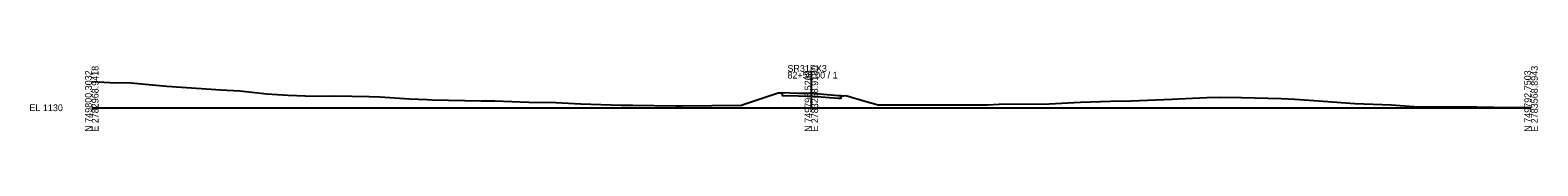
# Model space of a CAD drawing. Extents: x 1199974 to 1204603, y 1199988 to 1202535.
# Drawn here: x 1203974 to 1204603, y 1201490 to 1201518 of the extents above; entities that cross this region are included whole.
import ezdxf

# ---------------------------------------------------------------- set-up
doc = ezdxf.new("R2010")
doc.units = 0
for name, color, linetype in [('Section', 7, 'Continuous'), ('SURVEY - DTM GRAPHICS - Triangles', 7, 'Continuous'), ('SURVEY - TRANSPORTATION - Features', 7, 'Continuous'), ('XSCell', 7, 'Continuous')]:
    doc.layers.add(name, color=color, linetype=linetype)

msp = doc.modelspace()

# ---------------------------------------------------------------- linework, layer by layer
at = {"layer": 'SURVEY - DTM GRAPHICS - Triangles'}
for points in [[(1204000, 1201510.95), (1204007.52, 1201510.54), (1204016.42, 1201510.36), (1204017.78, 1201510.23), (1204031.32, 1201508.94), (1204053.76, 1201507.5), (1204059.13, 1201507.19), (1204061.69, 1201507.01), (1204072.99, 1201505.86), (1204081.91, 1201505.29), (1204092.53, 1201504.81), (1204101.17, 1201505), (1204115.62, 1201504.76), (1204120.15, 1201504.54), (1204132.44, 1201503.79), (1204139.75, 1201503.45), (1204141.88, 1201503.35), (1204162.35, 1201502.94), (1204168.08, 1201502.85), (1204182.13, 1201502.29), (1204193.45, 1201502.14), (1204203.82, 1201501.7), (1204220.71, 1201501.14), (1204225.49, 1201501.02), (1204243.49, 1201500.83), (1204245.31, 1201500.82), (1204246.19, 1201500.81), (1204270.79, 1201501.1), (1204272.33, 1201501.69), (1204286.11, 1201506.18), (1204287.09, 1201506.17), (1204287.85, 1201506.17)], [(1204312.36, 1201504.96), (1204312.72, 1201504.97), (1204312.99, 1201504.99), (1204313.56, 1201505.01), (1204314.3, 1201505.06), (1204322.89, 1201502.65), (1204327.87, 1201501.25), (1204337.19, 1201501.27), (1204347.94, 1201501.29), (1204356.83, 1201501.28), (1204373.46, 1201501.29), (1204378.3, 1201501.48), (1204399.08, 1201501.68), (1204412.21, 1201502.31), (1204424.71, 1201502.77), (1204433.12, 1201502.96), (1204450.34, 1201503.59), (1204453.06, 1201503.77), (1204464.9, 1201504.23), (1204470.61, 1201504.42), (1204479.25, 1201504.26), (1204495.89, 1201503.92), (1204501.54, 1201503.56), (1204509.63, 1201503.04), (1204526.58, 1201501.8), (1204541.63, 1201501.19), (1204551.17, 1201500.51), (1204575.44, 1201500.4), (1204577.41, 1201500.36), (1204584.48, 1201500.32), (1204598.38, 1201500.15), (1204600, 1201500.17)]]:
    msp.add_lwpolyline(points, dxfattribs=at)
at = {"layer": 'SURVEY - TRANSPORTATION - Features'}
msp.add_lwpolyline([(1204287.85, 1201506.17), (1204287.85, 1201505.17), (1204294.6, 1201505.01), (1204300.41, 1201504.89), (1204311.22, 1201504.04), (1204312.36, 1201503.96), (1204312.36, 1201504.96), (1204311.22, 1201505.04), (1204300.41, 1201505.89), (1204294.6, 1201506.01), (1204287.85, 1201506.17)], dxfattribs=at)
at = {"layer": 'XSCell'}
for p, q in [((1204300, 1201500), (1204300, 1201515)), ((1204000, 1201500), (1204300, 1201500)), ((1204300, 1201500), (1204600, 1201500))]:
    msp.add_line(p, q, dxfattribs=at)

# ---------------------------------------------------------------- texts
at = {"layer": 'Section'}
msp.add_text('-', height=0.0001, dxfattribs=at).set_placement((1204000, 1201500))
at = {"layer": 'XSCell'}
for s, p in [('E 2782968.9418', (1204002.8, 1201490)), ('E 2783268.9180', (1204302.8, 1201490)), ('E 2783568.8943', (1204602.8, 1201490)), ('N 749800.3032', (1204000, 1201490)), ('N 749796.5268', (1204300, 1201490)), ('N 749792.7503', (1204600, 1201490))]:
    msp.add_text(s, height=2.8, rotation=90, dxfattribs=at).set_placement(p)
for s, p in [('SR31EX3', (1204290, 1201515)), ('82+50.00 / 1', (1204290, 1201512.2)), ('EL 1130', (1203974, 1201498.6))]:
    msp.add_text(s, height=2.8, dxfattribs=at).set_placement(p)

doc.saveas('drawing.dxf')
